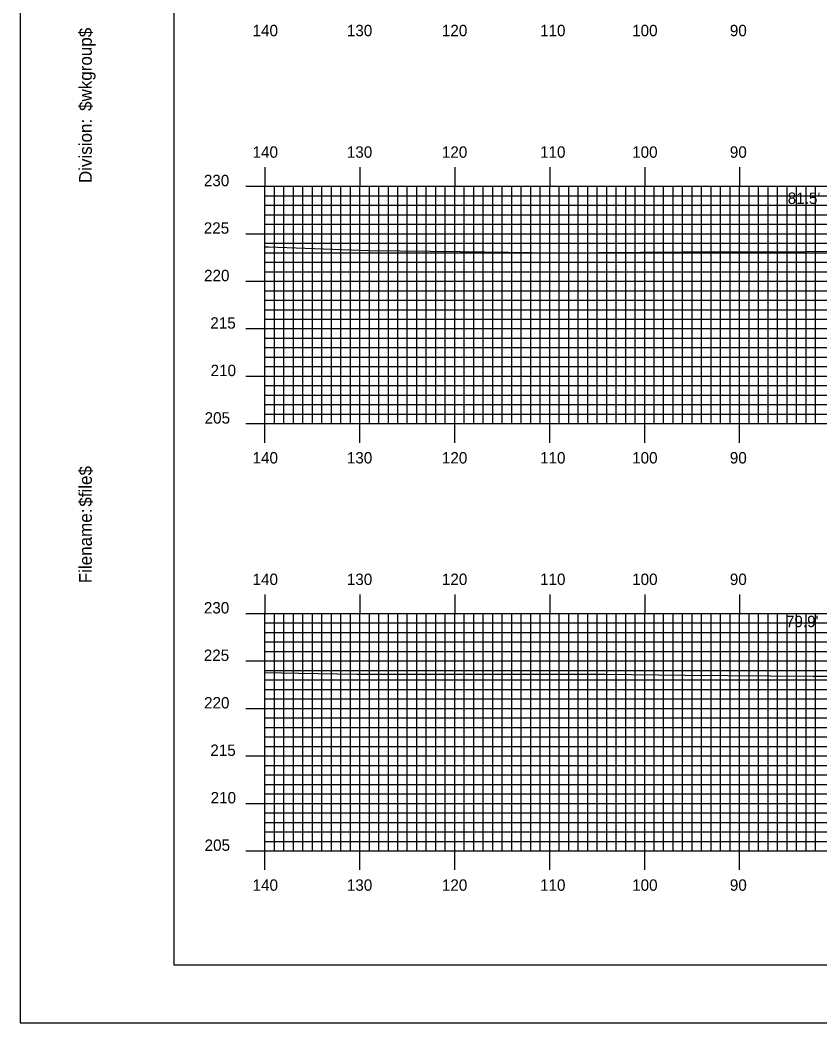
# Model space of a CAD drawing. Extents: x 1820818 to 1821161, y 442591 to 442811.
# Drawn here: x 1820817.9 to 1820902.2, y 442590.5 to 442696.2 of the extents above; entities that cross this region are included whole.
import ezdxf

# ---------------------------------------------------------------- set-up
doc = ezdxf.new("R2010")
doc.units = 0
for name, color, linetype in [('BORDER', 7, 'Continuous'), ('D_Text_Standard', 7, 'Continuous'), ('H_V ANNOTATION', 7, 'Continuous'), ('MAJOR', 7, 'Continuous'), ('MINOR', 7, 'Continuous'), ('PLOT BOUNDARY', 7, 'Continuous'), ('S_Roadway_Centerline', 7, 'Continuous')]:
    doc.layers.add(name, color=color, linetype=linetype)

msp = doc.modelspace()

# ---------------------------------------------------------------- linework, layer by layer
at = {"layer": 'BORDER'}
msp.add_lwpolyline([(1820834.12, 442596.67), (1821154.12, 442596.67), (1821154.12, 442806.67), (1820834.12, 442806.67)], close=True, dxfattribs=at)
at = {"layer": 'MAJOR'}
for p, q in [((1820843.72, 442680.67), (1820843.72, 442678.67)), ((1820853.72, 442680.67), (1820853.72, 442678.67)), ((1820863.72, 442680.67), (1820863.72, 442678.67)), ((1820873.72, 442680.67), (1820873.72, 442678.67)), ((1820883.72, 442680.67), (1820883.72, 442678.67)), ((1820893.72, 442680.67), (1820893.72, 442678.67)), ((1820841.71, 442678.67), (1820843.72, 442678.67)), ((1820843.72, 442678.67), (1821123.72, 442678.67)), ((1820843.72, 442653.67), (1820843.72, 442678.67)), ((1820843.72, 442653.67), (1820843.72, 442678.67)), ((1820843.72, 442678.67), (1821123.72, 442678.67)), ((1820853.72, 442653.67), (1820853.72, 442678.67)), ((1820863.72, 442653.67), (1820863.72, 442678.67)), ((1820873.72, 442653.67), (1820873.72, 442678.67)), ((1820883.72, 442653.67), (1820883.72, 442678.67)), ((1820893.72, 442653.67), (1820893.72, 442678.67)), ((1820841.71, 442673.67), (1820843.72, 442673.67)), ((1820843.72, 442673.67), (1821123.72, 442673.67)), ((1820841.71, 442668.67), (1820843.72, 442668.67)), ((1820843.72, 442668.67), (1821123.72, 442668.67)), ((1820841.71, 442663.67), (1820843.72, 442663.67)), ((1820843.72, 442663.67), (1821123.72, 442663.67)), ((1820841.71, 442658.67), (1820843.72, 442658.67)), ((1820843.72, 442658.67), (1821123.72, 442658.67)), ((1820841.71, 442653.67), (1820843.72, 442653.67)), ((1820843.72, 442653.67), (1821123.72, 442653.67)), ((1820843.72, 442653.67), (1821123.72, 442653.67)), ((1820843.72, 442651.66), (1820843.72, 442653.67)), ((1820853.72, 442651.66), (1820853.72, 442653.67)), ((1820863.72, 442651.66), (1820863.72, 442653.67)), ((1820873.72, 442651.66), (1820873.72, 442653.67)), ((1820883.72, 442651.66), (1820883.72, 442653.67)), ((1820893.72, 442651.66), (1820893.72, 442653.67)), ((1820843.72, 442635.67), (1820843.72, 442633.67)), ((1820853.72, 442635.67), (1820853.72, 442633.67)), ((1820863.72, 442635.67), (1820863.72, 442633.67)), ((1820873.72, 442635.67), (1820873.72, 442633.67)), ((1820883.72, 442635.67), (1820883.72, 442633.67)), ((1820893.72, 442635.67), (1820893.72, 442633.67)), ((1820841.71, 442633.67), (1820843.72, 442633.67)), ((1820843.72, 442633.67), (1821123.72, 442633.67)), ((1820843.72, 442608.67), (1820843.72, 442633.67)), ((1820843.72, 442608.67), (1820843.72, 442633.67)), ((1820843.72, 442633.67), (1821123.72, 442633.67)), ((1820853.72, 442608.67), (1820853.72, 442633.67)), ((1820863.72, 442608.67), (1820863.72, 442633.67)), ((1820873.72, 442608.67), (1820873.72, 442633.67)), ((1820883.72, 442608.67), (1820883.72, 442633.67)), ((1820893.72, 442608.67), (1820893.72, 442633.67)), ((1820841.71, 442628.67), (1820843.72, 442628.67)), ((1820843.72, 442628.67), (1821123.72, 442628.67)), ((1820841.71, 442623.67), (1820843.72, 442623.67)), ((1820843.72, 442623.67), (1821123.72, 442623.67)), ((1820841.71, 442618.67), (1820843.72, 442618.67)), ((1820843.72, 442618.67), (1821123.72, 442618.67)), ((1820841.71, 442613.67), (1820843.72, 442613.67)), ((1820843.72, 442613.67), (1821123.72, 442613.67)), ((1820841.71, 442608.67), (1820843.72, 442608.67)), ((1820843.72, 442608.67), (1821123.72, 442608.67)), ((1820843.72, 442608.67), (1821123.72, 442608.67)), ((1820843.72, 442606.66), (1820843.72, 442608.67)), ((1820853.72, 442606.66), (1820853.72, 442608.67)), ((1820863.72, 442606.66), (1820863.72, 442608.67)), ((1820873.72, 442606.66), (1820873.72, 442608.67)), ((1820883.72, 442606.66), (1820883.72, 442608.67)), ((1820893.72, 442606.66), (1820893.72, 442608.67))]:
    msp.add_line(p, q, dxfattribs=at)
at = {"layer": 'MINOR'}
for p, q in [((1820844.72, 442653.67), (1820844.72, 442678.67)), ((1820845.72, 442653.67), (1820845.72, 442678.67)), ((1820846.72, 442653.67), (1820846.72, 442678.67)), ((1820847.72, 442653.67), (1820847.72, 442678.67)), ((1820848.72, 442653.67), (1820848.72, 442678.67)), ((1820849.72, 442653.67), (1820849.72, 442678.67)), ((1820850.72, 442653.67), (1820850.72, 442678.67)), ((1820851.72, 442653.67), (1820851.72, 442678.67)), ((1820852.72, 442653.67), (1820852.72, 442678.67)), ((1820854.72, 442653.67), (1820854.72, 442678.67)), ((1820855.72, 442653.67), (1820855.72, 442678.67)), ((1820856.72, 442653.67), (1820856.72, 442678.67)), ((1820857.72, 442653.67), (1820857.72, 442678.67)), ((1820858.72, 442653.67), (1820858.72, 442678.67)), ((1820859.72, 442653.67), (1820859.72, 442678.67)), ((1820860.72, 442653.67), (1820860.72, 442678.67)), ((1820861.72, 442653.67), (1820861.72, 442678.67)), ((1820862.72, 442653.67), (1820862.72, 442678.67)), ((1820864.72, 442653.67), (1820864.72, 442678.67)), ((1820865.72, 442653.67), (1820865.72, 442678.67)), ((1820866.72, 442653.67), (1820866.72, 442678.67)), ((1820867.72, 442653.67), (1820867.72, 442678.67)), ((1820868.72, 442653.67), (1820868.72, 442678.67)), ((1820869.72, 442653.67), (1820869.72, 442678.67)), ((1820870.72, 442653.67), (1820870.72, 442678.67)), ((1820871.72, 442653.67), (1820871.72, 442678.67)), ((1820872.72, 442653.67), (1820872.72, 442678.67)), ((1820874.72, 442653.67), (1820874.72, 442678.67)), ((1820875.72, 442653.67), (1820875.72, 442678.67)), ((1820876.72, 442653.67), (1820876.72, 442678.67)), ((1820877.72, 442653.67), (1820877.72, 442678.67)), ((1820878.72, 442653.67), (1820878.72, 442678.67)), ((1820879.72, 442653.67), (1820879.72, 442678.67)), ((1820880.72, 442653.67), (1820880.72, 442678.67)), ((1820881.72, 442653.67), (1820881.72, 442678.67)), ((1820882.72, 442653.67), (1820882.72, 442678.67)), ((1820884.72, 442653.67), (1820884.72, 442678.67)), ((1820885.72, 442653.67), (1820885.72, 442678.67)), ((1820886.72, 442653.67), (1820886.72, 442678.67)), ((1820887.72, 442653.67), (1820887.72, 442678.67)), ((1820888.72, 442653.67), (1820888.72, 442678.67)), ((1820889.72, 442653.67), (1820889.72, 442678.67)), ((1820890.72, 442653.67), (1820890.72, 442678.67)), ((1820891.72, 442653.67), (1820891.72, 442678.67)), ((1820892.72, 442653.67), (1820892.72, 442678.67)), ((1820894.72, 442653.67), (1820894.72, 442678.67)), ((1820895.72, 442653.67), (1820895.72, 442678.67)), ((1820896.72, 442653.67), (1820896.72, 442678.67)), ((1820897.72, 442653.67), (1820897.72, 442678.67)), ((1820898.72, 442653.67), (1820898.72, 442678.67)), ((1820899.72, 442653.67), (1820899.72, 442678.67)), ((1820900.72, 442653.67), (1820900.72, 442678.67)), ((1820901.72, 442653.67), (1820901.72, 442678.67)), ((1820843.72, 442677.67), (1821123.72, 442677.67)), ((1820843.72, 442677.67), (1820845.72, 442677.67)), ((1820843.72, 442676.67), (1821123.72, 442676.67)), ((1820843.72, 442676.67), (1820845.72, 442676.67)), ((1820843.72, 442675.67), (1821123.72, 442675.67)), ((1820843.72, 442675.67), (1820845.72, 442675.67)), ((1820843.72, 442674.67), (1821123.72, 442674.67)), ((1820843.72, 442674.67), (1820845.72, 442674.67)), ((1820843.72, 442672.67), (1821123.72, 442672.67)), ((1820843.72, 442672.67), (1820845.72, 442672.67)), ((1820843.72, 442671.67), (1821123.72, 442671.67)), ((1820843.72, 442671.67), (1820845.72, 442671.67)), ((1820843.72, 442670.67), (1821123.72, 442670.67)), ((1820843.72, 442670.67), (1820845.72, 442670.67)), ((1820843.72, 442669.67), (1821123.72, 442669.67)), ((1820843.72, 442669.67), (1820845.72, 442669.67)), ((1820843.72, 442667.67), (1821123.72, 442667.67)), ((1820843.72, 442667.67), (1820845.72, 442667.67)), ((1820843.72, 442666.67), (1821123.72, 442666.67)), ((1820843.72, 442666.67), (1820845.72, 442666.67)), ((1820843.72, 442665.67), (1821123.72, 442665.67)), ((1820843.72, 442665.67), (1820845.72, 442665.67)), ((1820843.72, 442664.67), (1821123.72, 442664.67)), ((1820843.72, 442664.67), (1820845.72, 442664.67)), ((1820843.72, 442662.67), (1821123.72, 442662.67)), ((1820843.72, 442662.67), (1820845.72, 442662.67)), ((1820843.72, 442661.67), (1821123.72, 442661.67)), ((1820843.72, 442661.67), (1820845.72, 442661.67)), ((1820843.72, 442660.67), (1821123.72, 442660.67)), ((1820843.72, 442660.67), (1820845.72, 442660.67)), ((1820843.72, 442659.67), (1821123.72, 442659.67)), ((1820843.72, 442659.67), (1820845.72, 442659.67)), ((1820843.72, 442657.67), (1821123.72, 442657.67)), ((1820843.72, 442657.67), (1820845.72, 442657.67)), ((1820843.72, 442656.67), (1821123.72, 442656.67)), ((1820843.72, 442656.67), (1820845.72, 442656.67)), ((1820843.72, 442655.67), (1821123.72, 442655.67)), ((1820843.72, 442655.67), (1820845.72, 442655.67)), ((1820843.72, 442654.67), (1821123.72, 442654.67)), ((1820843.72, 442654.67), (1820845.72, 442654.67)), ((1820844.72, 442608.67), (1820844.72, 442633.67)), ((1820845.72, 442608.67), (1820845.72, 442633.67)), ((1820846.72, 442608.67), (1820846.72, 442633.67)), ((1820847.72, 442608.67), (1820847.72, 442633.67)), ((1820848.72, 442608.67), (1820848.72, 442633.67)), ((1820849.72, 442608.67), (1820849.72, 442633.67)), ((1820850.72, 442608.67), (1820850.72, 442633.67)), ((1820851.72, 442608.67), (1820851.72, 442633.67)), ((1820852.72, 442608.67), (1820852.72, 442633.67)), ((1820854.72, 442608.67), (1820854.72, 442633.67)), ((1820855.72, 442608.67), (1820855.72, 442633.67)), ((1820856.72, 442608.67), (1820856.72, 442633.67)), ((1820857.72, 442608.67), (1820857.72, 442633.67)), ((1820858.72, 442608.67), (1820858.72, 442633.67)), ((1820859.72, 442608.67), (1820859.72, 442633.67)), ((1820860.72, 442608.67), (1820860.72, 442633.67)), ((1820861.72, 442608.67), (1820861.72, 442633.67)), ((1820862.72, 442608.67), (1820862.72, 442633.67)), ((1820864.72, 442608.67), (1820864.72, 442633.67)), ((1820865.72, 442608.67), (1820865.72, 442633.67)), ((1820866.72, 442608.67), (1820866.72, 442633.67)), ((1820867.72, 442608.67), (1820867.72, 442633.67)), ((1820868.72, 442608.67), (1820868.72, 442633.67)), ((1820869.72, 442608.67), (1820869.72, 442633.67)), ((1820870.72, 442608.67), (1820870.72, 442633.67)), ((1820871.72, 442608.67), (1820871.72, 442633.67)), ((1820872.72, 442608.67), (1820872.72, 442633.67)), ((1820874.72, 442608.67), (1820874.72, 442633.67)), ((1820875.72, 442608.67), (1820875.72, 442633.67)), ((1820876.72, 442608.67), (1820876.72, 442633.67)), ((1820877.72, 442608.67), (1820877.72, 442633.67)), ((1820878.72, 442608.67), (1820878.72, 442633.67)), ((1820879.72, 442608.67), (1820879.72, 442633.67)), ((1820880.72, 442608.67), (1820880.72, 442633.67)), ((1820881.72, 442608.67), (1820881.72, 442633.67)), ((1820882.72, 442608.67), (1820882.72, 442633.67)), ((1820884.72, 442608.67), (1820884.72, 442633.67)), ((1820885.72, 442608.67), (1820885.72, 442633.67)), ((1820886.72, 442608.67), (1820886.72, 442633.67)), ((1820887.72, 442608.67), (1820887.72, 442633.67)), ((1820888.72, 442608.67), (1820888.72, 442633.67)), ((1820889.72, 442608.67), (1820889.72, 442633.67)), ((1820890.72, 442608.67), (1820890.72, 442633.67)), ((1820891.72, 442608.67), (1820891.72, 442633.67)), ((1820892.72, 442608.67), (1820892.72, 442633.67)), ((1820894.72, 442608.67), (1820894.72, 442633.67)), ((1820895.72, 442608.67), (1820895.72, 442633.67)), ((1820896.72, 442608.67), (1820896.72, 442633.67)), ((1820897.72, 442608.67), (1820897.72, 442633.67)), ((1820898.72, 442608.67), (1820898.72, 442633.67)), ((1820899.72, 442608.67), (1820899.72, 442633.67)), ((1820900.72, 442608.67), (1820900.72, 442633.67)), ((1820901.72, 442608.67), (1820901.72, 442633.67)), ((1820843.72, 442632.67), (1821123.72, 442632.67)), ((1820843.72, 442632.67), (1820845.72, 442632.67)), ((1820843.72, 442631.67), (1821123.72, 442631.67)), ((1820843.72, 442631.67), (1820845.72, 442631.67)), ((1820843.72, 442630.67), (1821123.72, 442630.67)), ((1820843.72, 442630.67), (1820845.72, 442630.67)), ((1820843.72, 442629.67), (1821123.72, 442629.67)), ((1820843.72, 442629.67), (1820845.72, 442629.67)), ((1820843.72, 442627.67), (1821123.72, 442627.67)), ((1820843.72, 442627.67), (1820845.72, 442627.67)), ((1820843.72, 442626.67), (1821123.72, 442626.67)), ((1820843.72, 442626.67), (1820845.72, 442626.67)), ((1820843.72, 442625.67), (1821123.72, 442625.67)), ((1820843.72, 442625.67), (1820845.72, 442625.67)), ((1820843.72, 442624.67), (1821123.72, 442624.67)), ((1820843.72, 442624.67), (1820845.72, 442624.67)), ((1820843.72, 442622.67), (1821123.72, 442622.67)), ((1820843.72, 442622.67), (1820845.72, 442622.67)), ((1820843.72, 442621.67), (1821123.72, 442621.67)), ((1820843.72, 442621.67), (1820845.72, 442621.67)), ((1820843.72, 442620.67), (1821123.72, 442620.67)), ((1820843.72, 442620.67), (1820845.72, 442620.67)), ((1820843.72, 442619.67), (1821123.72, 442619.67)), ((1820843.72, 442619.67), (1820845.72, 442619.67)), ((1820843.72, 442617.67), (1821123.72, 442617.67)), ((1820843.72, 442617.67), (1820845.72, 442617.67)), ((1820843.72, 442616.67), (1821123.72, 442616.67)), ((1820843.72, 442616.67), (1820845.72, 442616.67)), ((1820843.72, 442615.67), (1821123.72, 442615.67)), ((1820843.72, 442615.67), (1820845.72, 442615.67)), ((1820843.72, 442614.67), (1821123.72, 442614.67)), ((1820843.72, 442614.67), (1820845.72, 442614.67)), ((1820843.72, 442612.67), (1821123.72, 442612.67)), ((1820843.72, 442612.67), (1820845.72, 442612.67)), ((1820843.72, 442611.67), (1821123.72, 442611.67)), ((1820843.72, 442611.67), (1820845.72, 442611.67)), ((1820843.72, 442610.67), (1821123.72, 442610.67)), ((1820843.72, 442610.67), (1820845.72, 442610.67)), ((1820843.72, 442609.67), (1821123.72, 442609.67)), ((1820843.72, 442609.67), (1820845.72, 442609.67))]:
    msp.add_line(p, q, dxfattribs=at)
at = {"layer": 'PLOT BOUNDARY'}
msp.add_lwpolyline([(1820817.93, 442590.55), (1821157.93, 442590.55), (1821157.93, 442810.55), (1820817.93, 442810.55)], close=True, dxfattribs=at)
at = {"layer": 'S_Roadway_Centerline'}
for points in [[(1820843.72, 442672.3), (1820844.11, 442672.29), (1820854.74, 442671.9), (1820864.31, 442671.78), (1820874.39, 442671.67), (1820887.74, 442671.75), (1820897.44, 442671.77), (1820906.98, 442671.88), (1820930.49, 442671.78), (1820956.79, 442671.27), (1820959.09, 442671.32), (1820962.35, 442671.22), (1820975.01, 442671), (1820975.43, 442670.99), (1820991.07, 442670.68), (1820998.78, 442670.49), (1821009.44, 442670.25), (1821021.98, 442670.01)], [(1820843.72, 442627.44), (1820847.28, 442627.37), (1820853.39, 442627.27), (1820866.09, 442627.29), (1820870.53, 442627.29), (1820879.54, 442627.29), (1820888, 442627.19), (1820901.45, 442627.07), (1820906.36, 442627.07), (1820913.64, 442627.08), (1820920.92, 442627.11), (1820923.26, 442627.42), (1820936.46, 442628.65), (1820946.85, 442627.34), (1820954.79, 442626.43), (1820968.88, 442626.11), (1820971.93, 442625.99), (1820973.61, 442625.96), (1820992.48, 442625.84), (1820996.3, 442625.75), (1821006.07, 442625.62), (1821014.13, 442625.62), (1821023.16, 442625.59)]]:
    msp.add_lwpolyline(points, dxfattribs=at)

# ---------------------------------------------------------------- texts
at = {"layer": 'BORDER'}
for s, p in [('$wkgroup$', (1820825.49, 442686.6)), ('Division:', (1820825.49, 442679)), ('$file$', (1820825.49, 442644.92)), ('Filename:', (1820825.49, 442636.86))]:
    msp.add_text(s, height=1.339, rotation=90, dxfattribs=at).set_placement(p)
at = {"layer": 'D_Text_Standard'}
for s, p in [("81.5'", (1820898.79, 442676.81)), ("79.9'", (1820898.6, 442632.23))]:
    msp.add_text(s, height=1.2, dxfattribs=at).set_placement(p)
at = {"layer": 'H_V ANNOTATION'}
for s, p in [('140', (1820842.42, 442694.47)), ('130', (1820852.35, 442694.47)), ('120', (1820862.36, 442694.47)), ('110', (1820872.7, 442694.47)), ('100', (1820882.4, 442694.47)), ('90', (1820892.69, 442694.47)), ('140', (1820842.42, 442681.67)), ('130', (1820852.35, 442681.67)), ('120', (1820862.36, 442681.67)), ('110', (1820872.7, 442681.67)), ('100', (1820882.4, 442681.67)), ('90', (1820892.69, 442681.67)), ('230', (1820837.29, 442678.67)), ('225', (1820837.28, 442673.67)), ('220', (1820837.31, 442668.67)), ('215', (1820837.97, 442663.67)), ('210', (1820838, 442658.67)), ('205', (1820837.37, 442653.67)), ('140', (1820842.42, 442649.47)), ('130', (1820852.35, 442649.47)), ('120', (1820862.36, 442649.47)), ('110', (1820872.7, 442649.47)), ('100', (1820882.4, 442649.47)), ('90', (1820892.69, 442649.47)), ('140', (1820842.42, 442636.67)), ('130', (1820852.35, 442636.67)), ('120', (1820862.36, 442636.67)), ('110', (1820872.7, 442636.67)), ('100', (1820882.4, 442636.67)), ('90', (1820892.69, 442636.67)), ('230', (1820837.29, 442633.67)), ('225', (1820837.28, 442628.67)), ('220', (1820837.31, 442623.67)), ('215', (1820837.97, 442618.67)), ('210', (1820838, 442613.67)), ('205', (1820837.37, 442608.67)), ('140', (1820842.42, 442604.47)), ('130', (1820852.35, 442604.47)), ('120', (1820862.36, 442604.47)), ('110', (1820872.7, 442604.47)), ('100', (1820882.4, 442604.47)), ('90', (1820892.69, 442604.47))]:
    msp.add_text(s, height=1.2, dxfattribs=at).set_placement(p)
at = {"layer": 'MAJOR'}
for p in [(1820843.71, 442653.67), (1820843.71, 442608.67)]:
    msp.add_text('-', height=0.012, dxfattribs=at).set_placement(p)

doc.saveas('drawing.dxf')
